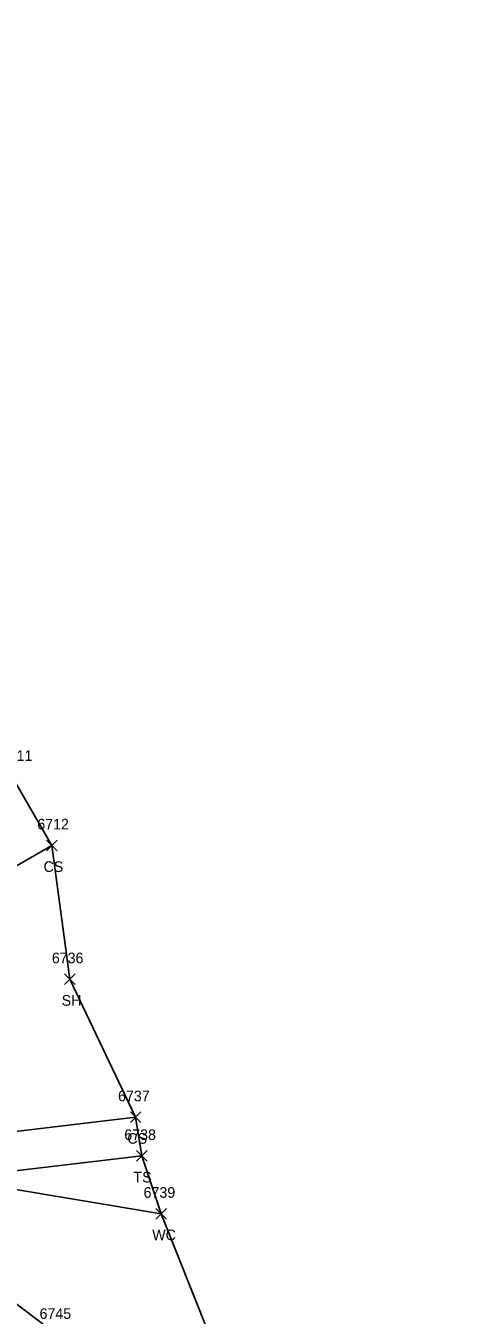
# Model space of a CAD drawing. Extents: x 1472233 to 1475777, y 540726 to 543442.
# Drawn here: x 1472877 to 1472960.9, y 541477.9 to 541720.8 of the extents above; entities that cross this region are included whole.
import ezdxf

# ---------------------------------------------------------------- set-up
doc = ezdxf.new("R2010")
doc.units = 0
for name, color, linetype in [('L_A', 7, 'Continuous'), ('L_I', 7, 'Continuous'), ('L_TIC', 7, 'Continuous'), ('LAWE', 7, 'Continuous'), ('LELB', 7, 'Continuous'), ('LSOGP', 7, 'Continuous')]:
    doc.layers.add(name, color=color, linetype=linetype)

msp = doc.modelspace()

# ---------------------------------------------------------------- linework, layer by layer
at = {"layer": 'L_TIC'}
for points in [[(1472880.95, 541565.38), (1472882.95, 541567.38)], [(1472882.95, 541565.38), (1472880.95, 541567.38)], [(1472884.31, 541540.17), (1472886.31, 541542.17)], [(1472886.31, 541540.17), (1472884.31, 541542.17)], [(1472896.73, 541514.17), (1472898.73, 541516.17)], [(1472898.73, 541514.17), (1472896.73, 541516.17)], [(1472897.91, 541506.88), (1472899.91, 541508.88)], [(1472899.91, 541506.88), (1472897.91, 541508.88)], [(1472901.55, 541495.99), (1472903.55, 541497.99)], [(1472903.55, 541495.99), (1472901.55, 541497.99)]]:
    msp.add_lwpolyline(points, dxfattribs=at)
at = {"layer": 'LAWE'}
for points in [[(1472863.45, 541597.21), (1472846.01, 541580.2), (1472821.69, 541564.77), (1472799.89, 541552.55), (1472793.15, 541544.39), (1472801.07, 541529.07), (1472814.13, 541525.02), (1472819.06, 541508.81), (1472826.65, 541500.5), (1472839.35, 541501.32), (1472847.01, 541503), (1472872.12, 541502.08), (1472902.55, 541496.99)], [(1472882.95, 541474.17), (1472870.99, 541483.19), (1472847.23, 541493.63), (1472828.43, 541488.51), (1472813.58, 541504.3), (1472805.11, 541508.45), (1472796.72, 541507.39), (1472789.44, 541501.79), (1472782.3, 541487.24), (1472749.95, 541469.27)]]:
    msp.add_lwpolyline(points, dxfattribs=at)
at = {"layer": 'LELB'}
for points in [[(1472864.77, 541595.77), (1472847.21, 541578.72), (1472821.69, 541564.77), (1472801.37, 541550.22), (1472800.02, 541544.17), (1472806.68, 541531.96), (1472817.48, 541530.36), (1472822.05, 541510.14), (1472831.29, 541503.45), (1472838.51, 541503.04), (1472846.77, 541505.78), (1472871.81, 541504.68), (1472898.91, 541507.88)], [(1472881.95, 541566.38), (1472860.67, 541554.14), (1472840.73, 541547.45), (1472825.71, 541538.53), (1472834.1, 541515.97), (1472869.27, 541511.77), (1472897.73, 541515.17)]]:
    msp.add_lwpolyline(points, dxfattribs=at)
at = {"layer": 'LSOGP'}
msp.add_lwpolyline([(1472823.77, 541743.14), (1472826.55, 541708.8), (1472845.91, 541656.61), (1472853.28, 541632.51), (1472849.75, 541618.72), (1472854.12, 541609.84), (1472858.88, 541602.25), (1472860.79, 541600.3), (1472863.45, 541597.21), (1472864.77, 541595.77), (1472874.51, 541579.29), (1472881.95, 541566.38), (1472885.31, 541541.17), (1472897.73, 541515.17), (1472898.91, 541507.88), (1472902.55, 541496.99), (1472920.36, 541452.21), (1472925.3, 541441.52), (1472946.07, 541415.68), (1472943.94, 541402.97), (1472977.95, 541382.17)], dxfattribs=at)

# ---------------------------------------------------------------- texts
at = {"layer": 'L_A'}
for s, p in [('CS', (1472880.39, 541561.38)), ('SH', (1472883.8, 541536.17)), ('CS', (1472896.17, 541510.17)), ('TS', (1472897.32, 541502.88)), ('WC', (1472900.85, 541491.99))]:
    msp.add_text(s, height=2, dxfattribs=at).set_placement(p)
at = {"layer": 'L_I'}
for s, p in [('6711', (1472872.34, 541582.29)), ('6712', (1472879.21, 541569.38)), ('6736', (1472881.95, 541544.17)), ('6737', (1472894.42, 541518.17)), ('6738', (1472895.6, 541510.88)), ('6739', (1472899.23, 541499.99)), ('6745', (1472879.64, 541477.17))]:
    msp.add_text(s, height=2, dxfattribs=at).set_placement(p)

doc.saveas('drawing.dxf')
